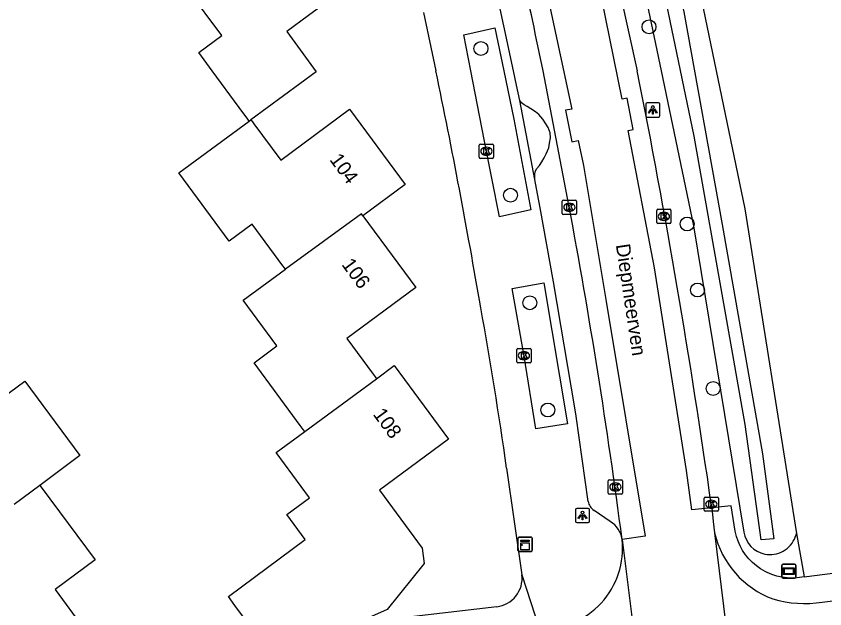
# Model space of a CAD drawing. Extents: x 163427 to 164190, y 380331 to 381641.
# Drawn here: x 163904.6 to 163961.5, y 381212.2 to 381253.8 of the extents above; entities that cross this region are included whole.
import ezdxf

# ---------------------------------------------------------------- set-up
doc = ezdxf.new("R2010")
doc.units = 0
for name, color, linetype in [('IMGEO_Boom', 7, 'Continuous'), ('IMGEO_Erf', 7, 'Continuous'), ('IMGEO_Groenvoorziening', 7, 'Continuous'), ('IMGEO_Kast', 7, 'Continuous'), ('IMGEO_Kolk', 7, 'Continuous'), ('IMGEO_Lichtpunt', 7, 'Continuous'), ('IMGEO_Openbare_ruimte_label', 7, 'Continuous'), ('IMGEO_Pand', 7, 'Continuous'), ('IMGEO_Pand_nummerreeks', 7, 'Continuous'), ('IMGEO_Parkeervlak_open', 7, 'Continuous'), ('IMGEO_Rijbaan_lokaal_gesloten', 7, 'Continuous'), ('IMGEO_Rijbaan_lokaal_open', 7, 'Continuous'), ('IMGEO_Straatnaambord', 7, 'Continuous'), ('IMGEO_Voetpad_open', 7, 'Continuous'), ('IMGEO_Waterloop', 7, 'Continuous')]:
    doc.layers.add(name, color=color, linetype=linetype)

msp = doc.modelspace()

# ---------------------------------------------------------------- linework, layer by layer
at = {"layer": 'IMGEO_Boom'}
for centre in [(163949.16, 381253.1), (163937.333, 381251.576), (163939.411, 381241.248), (163951.839, 381239.226), (163952.575, 381234.582), (163940.773, 381233.686), (163953.673, 381227.649), (163942.035, 381226.141)]:
    msp.add_circle(centre, 0.489, dxfattribs=at)
at = {"layer": 'IMGEO_Erf'}
msp.add_lwpolyline([(163946.949, 381280.126), (163950.911, 381264.377), (163953.894, 381250), (163955.908, 381240.291), (163959.527, 381217.462)], dxfattribs=at)
at = {"layer": 'IMGEO_Groenvoorziening'}
for points in [[(163946.949, 381280.126), (163944.591, 381279.658), (163943.768, 381279.495), (163943.73, 381277.607), (163947.625, 381261.424), (163950.014, 381250), (163952.296, 381239.088), (163955.838, 381217.536)], [(163957.309, 381216.003), (163957.474, 381215.976), (163957.642, 381215.964), (163957.809, 381215.967), (163957.976, 381215.985), (163958.14, 381216.018), (163958.301, 381216.066), (163958.457, 381216.127), (163958.606, 381216.202), (163958.749, 381216.291), (163958.883, 381216.391), (163959.007, 381216.503), (163959.121, 381216.626), (163959.223, 381216.759), (163959.314, 381216.9), (163959.391, 381217.049), (163959.455, 381217.204), (163959.504, 381217.364), (163959.527, 381217.462)], [(163959.527, 381217.462), (163960.076, 381214.403)]]:
    msp.add_lwpolyline(points, dxfattribs=at)
msp.add_arc((163957.687, 381217.838), 1.873, 189.2742, 258.3611, dxfattribs=at)
at = {"layer": 'IMGEO_Kast'}
for p, q in [((163939.939, 381216.261), (163939.939, 381217.102)), ((163939.939, 381217.102), (163939.939, 381216.261)), ((163940.014, 381217.186), (163940.855, 381217.186)), ((163940.855, 381217.186), (163940.014, 381217.186)), ((163940.939, 381217.111), (163940.939, 381216.27)), ((163940.939, 381216.27), (163940.939, 381217.111)), ((163940.864, 381216.186), (163940.023, 381216.186)), ((163940.023, 381216.186), (163940.864, 381216.186))]:
    msp.add_line(p, q, dxfattribs=at)
for points in [[(163940.134, 381216.976), (163940.734, 381216.976), (163940.734, 381216.891), (163940.134, 381216.891), (163940.134, 381216.976)], [(163940.134, 381216.801), (163940.734, 381216.801), (163940.734, 381216.312), (163940.134, 381216.312), (163940.134, 381216.801)]]:
    msp.add_lwpolyline(points, dxfattribs=at)
msp.add_circle((163940.218, 381216.65), 0.0377, dxfattribs=at)
for centre, start, end in [((163940.017, 381217.108), 92.4484, 184.2845), ((163940.017, 381217.108), 92.4484, 184.2845), ((163940.861, 381217.108), 2.4484, 94.2845), ((163940.861, 381217.108), 2.4484, 94.2845), ((163940.017, 381216.264), 182.4484, 274.2845), ((163940.017, 381216.264), 182.4484, 274.2845), ((163940.861, 381216.264), 272.4484, 4.2845), ((163940.861, 381216.264), 272.4484, 4.2845)]:
    msp.add_arc(centre, 0.0779, start, end, dxfattribs=at)
at = {"layer": 'IMGEO_Kolk'}
for p, q in [((163937.217, 381243.917), (163937.217, 381244.769)), ((163937.292, 381244.843), (163938.144, 381244.843)), ((163937.705, 381244.623), (163937.73, 381244.623)), ((163938.218, 381244.769), (163938.218, 381243.917)), ((163938.144, 381243.843), (163937.292, 381243.843)), ((163937.728, 381244.063), (163937.703, 381244.063)), ((163943.132, 381240.9), (163943.984, 381240.9)), ((163943.057, 381239.974), (163943.057, 381240.826)), ((163943.545, 381240.68), (163943.57, 381240.68)), ((163944.058, 381240.826), (163944.058, 381239.974)), ((163943.984, 381239.9), (163943.132, 381239.9)), ((163943.568, 381240.12), (163943.543, 381240.12)), ((163949.705, 381239.334), (163949.705, 381240.186)), ((163949.78, 381240.26), (163950.632, 381240.26)), ((163950.193, 381240.04), (163950.218, 381240.04)), ((163950.706, 381240.186), (163950.706, 381239.334)), ((163950.632, 381239.26), (163949.78, 381239.26)), ((163950.216, 381239.48), (163950.191, 381239.48)), ((163939.858, 381229.537), (163939.858, 381230.389)), ((163939.933, 381230.463), (163940.785, 381230.463)), ((163940.346, 381230.243), (163940.371, 381230.243)), ((163940.859, 381230.389), (163940.859, 381229.537)), ((163940.369, 381229.683), (163940.344, 381229.683)), ((163940.785, 381229.463), (163939.933, 381229.463)), ((163946.295, 381220.298), (163946.295, 381221.15)), ((163946.37, 381221.224), (163947.222, 381221.224)), ((163946.783, 381221.004), (163946.808, 381221.004)), ((163947.296, 381221.15), (163947.296, 381220.298)), ((163946.806, 381220.444), (163946.781, 381220.444)), ((163947.222, 381220.224), (163946.37, 381220.224)), ((163953.044, 381219.087), (163953.044, 381219.939)), ((163953.119, 381220.013), (163953.971, 381220.013)), ((163954.045, 381219.939), (163954.045, 381219.087)), ((163953.532, 381219.793), (163953.557, 381219.793)), ((163953.971, 381219.013), (163953.119, 381219.013)), ((163953.555, 381219.233), (163953.53, 381219.233))]:
    msp.add_line(p, q, dxfattribs=at)
for points in [[(163937.217, 381243.917), (163937.217, 381244.769)], [(163937.292, 381244.843), (163938.144, 381244.843)], [(163937.538, 381244.543), (163937.661, 381244.543), (163937.661, 381244.392), (163937.791, 381244.543), (163937.955, 381244.543), (163937.809, 381244.392), (163937.962, 381244.143), (163937.81, 381244.143), (163937.725, 381244.307), (163937.661, 381244.24), (163937.661, 381244.143), (163937.538, 381244.143), (163937.538, 381244.543)], [(163938.218, 381244.769), (163938.218, 381243.917)], [(163938.144, 381243.843), (163937.292, 381243.843)], [(163943.132, 381240.9), (163943.984, 381240.9)], [(163943.057, 381239.974), (163943.057, 381240.826)], [(163943.378, 381240.6), (163943.501, 381240.6), (163943.501, 381240.449), (163943.631, 381240.6), (163943.795, 381240.6), (163943.649, 381240.449), (163943.802, 381240.2), (163943.65, 381240.2), (163943.565, 381240.364), (163943.501, 381240.297), (163943.501, 381240.2), (163943.378, 381240.2), (163943.378, 381240.6)], [(163944.058, 381240.826), (163944.058, 381239.974)], [(163943.984, 381239.9), (163943.132, 381239.9)], [(163949.705, 381239.334), (163949.705, 381240.186)], [(163949.78, 381240.26), (163950.632, 381240.26)], [(163950.026, 381239.96), (163950.149, 381239.96), (163950.149, 381239.809), (163950.279, 381239.96), (163950.443, 381239.96), (163950.297, 381239.809), (163950.45, 381239.56), (163950.298, 381239.56), (163950.213, 381239.724), (163950.149, 381239.657), (163950.149, 381239.56), (163950.026, 381239.56), (163950.026, 381239.96)], [(163950.706, 381240.186), (163950.706, 381239.334)], [(163950.632, 381239.26), (163949.78, 381239.26)], [(163939.858, 381229.537), (163939.858, 381230.389)], [(163939.933, 381230.463), (163940.785, 381230.463)], [(163940.179, 381230.163), (163940.302, 381230.163), (163940.302, 381230.012), (163940.432, 381230.163), (163940.596, 381230.163), (163940.45, 381230.012), (163940.603, 381229.763), (163940.451, 381229.763), (163940.366, 381229.927), (163940.302, 381229.86), (163940.302, 381229.763), (163940.179, 381229.763), (163940.179, 381230.163)], [(163940.859, 381230.389), (163940.859, 381229.537)], [(163940.785, 381229.463), (163939.933, 381229.463)], [(163946.295, 381220.298), (163946.295, 381221.15)], [(163946.37, 381221.224), (163947.222, 381221.224)], [(163947.296, 381221.15), (163947.296, 381220.298)], [(163946.616, 381220.924), (163946.739, 381220.924), (163946.739, 381220.773), (163946.869, 381220.924), (163947.033, 381220.924), (163946.887, 381220.773), (163947.04, 381220.524), (163946.888, 381220.524), (163946.803, 381220.688), (163946.739, 381220.621), (163946.739, 381220.524), (163946.616, 381220.524), (163946.616, 381220.924)], [(163947.222, 381220.224), (163946.37, 381220.224)], [(163953.044, 381219.087), (163953.044, 381219.939)], [(163953.119, 381220.013), (163953.971, 381220.013)], [(163954.045, 381219.939), (163954.045, 381219.087)], [(163953.365, 381219.713), (163953.488, 381219.713), (163953.488, 381219.562), (163953.618, 381219.713), (163953.782, 381219.713), (163953.636, 381219.562), (163953.789, 381219.313), (163953.637, 381219.313), (163953.552, 381219.477), (163953.488, 381219.41), (163953.488, 381219.313), (163953.365, 381219.313), (163953.365, 381219.713)], [(163953.971, 381219.013), (163953.119, 381219.013)]]:
    msp.add_lwpolyline(points, dxfattribs=at)
for centre, start, end in [((163937.294, 381244.767), 91.552, 178.448), ((163937.294, 381244.767), 91.552, 178.448), ((163938.142, 381244.767), 1.552, 88.448), ((163938.142, 381244.767), 1.552, 88.448), ((163937.294, 381243.919), 181.552, 268.448), ((163937.294, 381243.919), 181.552, 268.448), ((163938.142, 381243.919), 271.552, 358.448), ((163938.142, 381243.919), 271.552, 358.448), ((163943.134, 381240.824), 91.552, 178.448), ((163943.134, 381240.824), 91.552, 178.448), ((163943.982, 381240.824), 1.552, 88.448), ((163943.982, 381240.824), 1.552, 88.448), ((163943.134, 381239.976), 181.552, 268.448), ((163943.134, 381239.976), 181.552, 268.448), ((163943.982, 381239.976), 271.552, 358.448), ((163943.982, 381239.976), 271.552, 358.448), ((163949.782, 381240.184), 91.552, 178.448), ((163949.782, 381240.184), 91.552, 178.448), ((163950.63, 381240.184), 1.552, 88.448), ((163950.63, 381240.184), 1.552, 88.448), ((163949.782, 381239.336), 181.552, 268.448), ((163949.782, 381239.336), 181.552, 268.448), ((163950.63, 381239.336), 271.552, 358.448), ((163950.63, 381239.336), 271.552, 358.448), ((163939.935, 381230.387), 91.552, 178.448), ((163939.935, 381230.387), 91.552, 178.448), ((163940.783, 381230.387), 1.552, 88.448), ((163940.783, 381230.387), 1.552, 88.448), ((163939.935, 381229.539), 181.552, 268.448), ((163939.935, 381229.539), 181.552, 268.448), ((163940.783, 381229.539), 271.552, 358.448), ((163940.783, 381229.539), 271.552, 358.448), ((163946.372, 381221.148), 91.552, 178.448), ((163946.372, 381221.148), 91.552, 178.448), ((163947.22, 381221.148), 1.552, 88.448), ((163947.22, 381221.148), 1.552, 88.448), ((163946.372, 381220.3), 181.552, 268.448), ((163946.372, 381220.3), 181.552, 268.448), ((163947.22, 381220.3), 271.552, 358.448), ((163947.22, 381220.3), 271.552, 358.448), ((163953.121, 381219.937), 91.552, 178.448), ((163953.121, 381219.937), 91.552, 178.448), ((163953.969, 381219.937), 1.552, 88.448), ((163953.969, 381219.937), 1.552, 88.448), ((163953.121, 381219.089), 181.552, 268.448), ((163953.121, 381219.089), 181.552, 268.448), ((163953.969, 381219.089), 271.552, 358.448), ((163953.969, 381219.089), 271.552, 358.448)]:
    msp.add_arc(centre, 0.0765, start, end, dxfattribs=at)
for centre, major_axis, ratio, start_param, end_param in [((163937.704, 381244.343), (-0.387, 0.002), 0.722429, 4.712389, 7.853982), ((163937.729, 381244.343), (-0.39, 0.002), 0.717154, 1.570796, 4.712389), ((163943.544, 381240.4), (-0.387, 0.002), 0.722429, 4.712389, 7.853982), ((163943.569, 381240.4), (-0.39, 0.002), 0.717154, 1.570796, 4.712389), ((163950.192, 381239.76), (-0.387, 0.002), 0.722429, 4.712389, 7.853982), ((163950.217, 381239.76), (-0.39, 0.002), 0.717154, 1.570796, 4.712389), ((163940.345, 381229.963), (-0.387, 0.002), 0.722429, 4.712389, 7.853982), ((163940.37, 381229.963), (-0.39, 0.002), 0.717154, 1.570796, 4.712389), ((163946.782, 381220.724), (-0.387, 0.002), 0.722429, 4.712389, 7.853982), ((163946.807, 381220.724), (-0.39, 0.002), 0.717154, 1.570796, 4.712389), ((163953.531, 381219.513), (-0.387, 0.002), 0.722429, 4.712389, 7.853982), ((163953.556, 381219.513), (-0.39, 0.002), 0.717154, 1.570796, 4.712389)]:
    msp.add_ellipse(centre, major_axis=major_axis, ratio=ratio, start_param=start_param, end_param=end_param, dxfattribs=at)
at = {"layer": 'IMGEO_Lichtpunt'}
for p, q in [((163949.828, 381247.749), (163949.02, 381247.749)), ((163949.828, 381247.749), (163949.02, 381247.749)), ((163948.926, 381247.654), (163948.926, 381246.847)), ((163948.926, 381247.654), (163948.926, 381246.847)), ((163949.922, 381246.847), (163949.922, 381247.654)), ((163949.922, 381246.847), (163949.922, 381247.654)), ((163949.02, 381246.753), (163949.828, 381246.753)), ((163949.02, 381246.753), (163949.828, 381246.753)), ((163943.978, 381219.119), (163943.978, 381218.312)), ((163943.978, 381219.119), (163943.978, 381218.312)), ((163944.88, 381219.214), (163944.072, 381219.214)), ((163944.88, 381219.214), (163944.072, 381219.214)), ((163944.974, 381218.312), (163944.974, 381219.119)), ((163944.974, 381218.312), (163944.974, 381219.119)), ((163944.072, 381218.218), (163944.88, 381218.218)), ((163944.072, 381218.218), (163944.88, 381218.218))]:
    msp.add_line(p, q, dxfattribs=at)
for points in [[(163949.3, 381247.318), (163949.339, 381247.29), (163949.151, 381247.028), (163949.113, 381247.055), (163949.3, 381247.318)], [(163949.402, 381247.27), (163949.449, 381247.27), (163949.449, 381246.948), (163949.402, 381246.948), (163949.402, 381247.27)], [(163949.512, 381247.29), (163949.55, 381247.317), (163949.737, 381247.055), (163949.698, 381247.027), (163949.512, 381247.29)], [(163944.352, 381218.783), (163944.391, 381218.755), (163944.203, 381218.493), (163944.165, 381218.52), (163944.352, 381218.783)], [(163944.454, 381218.735), (163944.501, 381218.735), (163944.501, 381218.413), (163944.454, 381218.413), (163944.454, 381218.735)], [(163944.564, 381218.755), (163944.602, 381218.782), (163944.789, 381218.52), (163944.75, 381218.492), (163944.564, 381218.755)]]:
    msp.add_lwpolyline(points, dxfattribs=at)
for centre in [(163949.425, 381247.452), (163944.477, 381218.917)]:
    msp.add_circle(centre, 0.0994, dxfattribs=at)
for centre, start, end in [((163949.02, 381247.654), 90, 180), ((163949.02, 381247.654), 90, 180), ((163949.828, 381247.654), 0, 90), ((163949.828, 381247.654), 0, 90), ((163949.02, 381246.847), 180, 270), ((163949.02, 381246.847), 180, 270), ((163949.828, 381246.847), 270, 0), ((163949.828, 381246.847), 270, 360), ((163944.072, 381219.119), 90, 180), ((163944.072, 381219.119), 90, 180), ((163944.88, 381219.119), 0, 90), ((163944.88, 381219.119), 0, 90), ((163944.072, 381218.312), 180, 270), ((163944.072, 381218.312), 180, 270), ((163944.88, 381218.312), 270, 0), ((163944.88, 381218.312), 270, 360)]:
    msp.add_arc(centre, 0.0946, start, end, dxfattribs=at)
at = {"layer": 'IMGEO_Pand'}
for points in [[(163923.541, 381260.701), (163925.042, 381261.788), (163928.858, 381256.586), (163925.203, 381253.905), (163923.664, 381252.776), (163925.746, 381249.938), (163921.142, 381246.559)], [(163921.018, 381246.468), (163920.924, 381246.596), (163920.319, 381247.421), (163918.427, 381250), (163917.477, 381251.296), (163919.089, 381252.478), (163916.694, 381255.744)], [(163921.142, 381246.559), (163921.255, 381246.406), (163921.349, 381246.279), (163923.241, 381243.723), (163928.087, 381247.31), (163932.004, 381242.003), (163929.027, 381239.809)], [(163921.018, 381246.468), (163921.142, 381246.559)], [(163923.577, 381236.038), (163923.501, 381236.141), (163923.394, 381236.286), (163921.229, 381239.216), (163919.623, 381238.029), (163916.069, 381242.837), (163921.018, 381246.468)], [(163929.027, 381239.809), (163928.932, 381239.938), (163923.577, 381236.038)], [(163929.027, 381239.809), (163932.757, 381234.753), (163927.885, 381231.164), (163929.745, 381228.65), (163929.881, 381228.466), (163929.973, 381228.341)], [(163924.929, 381224.636), (163924.829, 381224.772), (163924.62, 381225.054), (163921.364, 381229.46), (163922.97, 381230.647), (163920.592, 381233.864), (163923.577, 381236.038)], [(163929.973, 381228.341), (163931.237, 381229.27), (163935.058, 381224.076), (163930.198, 381220.5), (163933.192, 381216.427), (163933.327, 381215.334), (163930.724, 381212.101), (163925.359, 381209.706), (163922.998, 381208.373), (163920.026, 381212.394), (163919.557, 381213.029), (163924.967, 381217.028), (163923.674, 381218.778), (163925.279, 381219.965), (163922.918, 381223.159), (163924.929, 381224.636)], [(163900.412, 381228.801), (163902.419, 381226.093), (163905.23, 381228.176), (163909.118, 381222.931), (163906.302, 381220.836)], [(163924.929, 381224.636), (163929.973, 381228.341)], [(163906.302, 381220.836), (163904.482, 381219.482)], [(163906.302, 381220.836), (163906.393, 381220.713), (163910.185, 381215.595), (163907.365, 381213.506), (163909.376, 381210.792)]]:
    msp.add_lwpolyline(points, dxfattribs=at)
at = {"layer": 'IMGEO_Parkeervlak_open'}
msp.add_lwpolyline([(163941.127, 381242.354), (163941.114, 381242.759), (163941.176, 381242.958), (163941.275, 381243.128), (163941.449, 381243.349), (163941.628, 381243.606), (163941.79, 381243.879), (163941.918, 381244.152), (163942.101, 381244.584), (163942.162, 381244.903), (163942.224, 381245.288), (163942.215, 381245.638), (163942.058, 381246.015), (163941.891, 381246.283), (163941.684, 381246.607), (163941.4, 381246.924), (163941.171, 381247.114), (163940.853, 381247.321), (163940.597, 381247.483), (163940.368, 381247.607), (163940.194, 381247.75), (163940.062, 381247.913)], dxfattribs=at)
at = {"layer": 'IMGEO_Rijbaan_lokaal_gesloten'}
for points in [[(163912.249, 381359.295), (163913.697, 381359.629), (163921.907, 381330.645), (163925.185, 381318.778), (163924.817, 381318.679), (163925.405, 381316.489), (163925.802, 381316.596), (163930.68, 381299.334), (163933.228, 381290.176), (163942.098, 381254.961), (163943.722, 381247.313), (163943.287, 381247.227), (163943.726, 381245.01), (163944.183, 381245.1), (163944.552, 381243.335), (163946.144, 381233.78), (163948.882, 381217.269), (163947.265, 381217.038)], [(163953.57, 381219.255), (163952.161, 381219.119), (163951.806, 381221.884), (163949.541, 381236.14), (163947.702, 381245.797), (163948.052, 381245.866), (163947.613, 381248.083), (163947.279, 381248.017), (163944.361, 381262.334), (163940.492, 381277.062), (163941.823, 381277.416)], [(163941.823, 381277.416), (163942.486, 381274.934), (163944.765, 381266.145), (163948.335, 381250)], [(163943.519, 381240.555), (163941.708, 381250)], [(163953.54, 381219.513), (163953.57, 381219.255)], [(163953.57, 381219.255), (163953.683, 381218.285), (163953.779, 381217.501)], [(163947.265, 381217.038), (163949.305, 381200.709)], [(163953.779, 381217.501), (163955.843, 381200.674)]]:
    msp.add_lwpolyline(points, dxfattribs=at)
for centre, radius, start, end in [((163522.519, 381163.934), 427.933, 11.60247, 13.52023), ((163385.867, 381138.283), 573.456, 8.143357, 11.233859), ((163518.613, 381160.815), 432.324, 7.47236, 10.62875)]:
    msp.add_arc(centre, radius, start, end, dxfattribs=at)
at = {"layer": 'IMGEO_Rijbaan_lokaal_open'}
msp.add_lwpolyline([(163961.351, 381212.629), (163974.075, 381214.227)], dxfattribs=at)
for centre, radius, start, end in [((163941.609, 381216.413), 5.691, 268.4338, 6.3074), ((163960.137, 381218.969), 6.525, 193.0053, 249.7663), ((163960.095, 381220.375), 7.848, 253.604, 279.2084)]:
    msp.add_arc(centre, radius, start, end, dxfattribs=at)
at = {"layer": 'IMGEO_Straatnaambord'}
for p, q in [((163958.596, 381215.297), (163959.386, 381215.297)), ((163959.386, 381215.297), (163958.596, 381215.297)), ((163958.496, 381214.397), (163958.496, 381215.197)), ((163958.496, 381215.197), (163958.496, 381214.397)), ((163959.486, 381215.197), (163959.486, 381214.397)), ((163959.486, 381214.397), (163959.486, 381215.197)), ((163959.386, 381214.297), (163958.596, 381214.297)), ((163958.596, 381214.297), (163959.386, 381214.297))]:
    msp.add_line(p, q, dxfattribs=at)
for points in [[(163958.597, 381215.029), (163959.385, 381215.029), (163959.385, 381214.565), (163958.597, 381214.565), (163958.597, 381215.029)], [(163958.662, 381214.964), (163958.662, 381214.63), (163959.32, 381214.63), (163959.32, 381214.964), (163958.662, 381214.964)]]:
    msp.add_lwpolyline(points, dxfattribs=at)
for centre, start, end in [((163958.596, 381215.197), 90, 180), ((163958.596, 381215.197), 90, 180), ((163959.386, 381215.197), 0, 90), ((163959.386, 381215.197), 360, 90), ((163958.596, 381214.397), 180, 270), ((163958.596, 381214.397), 180, 270), ((163959.386, 381214.397), 270, 0), ((163959.386, 381214.397), 270, 0)]:
    msp.add_arc(centre, 0.1, start, end, dxfattribs=at)
at = {"layer": 'IMGEO_Voetpad_open'}
for points in [[(163940.062, 381247.913), (163939.835, 381248.988), (163939.627, 381250), (163938.955, 381253.175), (163937.51, 381259.832), (163936.359, 381264.784), (163935.892, 381266.688), (163934.592, 381271.826), (163933.019, 381277.636), (163931.635, 381282.748)], [(163933.3, 381254.106), (163934.167, 381250)], [(163938.305, 381253.03), (163938.938, 381250), (163939.646, 381246.606), (163940.84, 381240.228), (163938.639, 381239.731), (163937.567, 381245.174), (163936.622, 381250), (163936.125, 381252.542), (163938.305, 381253.03)], [(163941.127, 381242.354), (163940.062, 381247.913)], [(163944.882, 381219.713), (163944.027, 381225.716), (163943.966, 381226.145), (163942.427, 381235.164), (163941.491, 381240.359), (163941.313, 381241.342), (163941.127, 381242.354)], [(163941.75, 381235.096), (163943.423, 381225.172), (163941.191, 381224.82), (163940.366, 381229.927), (163939.539, 381234.696), (163941.75, 381235.096)], [(163939.142, 381222.056), (163940.216, 381214.537)], [(163960.076, 381214.403), (163959.414, 381214.318), (163959.234, 381214.313), (163958.87, 381214.328), (163958.508, 381214.376), (163958.152, 381214.455), (163957.805, 381214.566), (163957.469, 381214.708), (163957.324, 381214.781), (163957.01, 381214.964), (163956.713, 381215.175), (163956.436, 381215.411), (163956.182, 381215.672), (163955.952, 381215.954), (163955.748, 381216.255), (163955.571, 381216.574), (163955.424, 381216.907), (163955.308, 381217.251), (163955.222, 381217.605), (163954.949, 381219.4), (163953.57, 381219.255)], [(163946.432, 381218.288), (163945.289, 381219.077)], [(163960.076, 381214.403), (163973.754, 381216.166)], [(163940.216, 381214.537), (163941.453, 381210.724)], [(163938.44, 381212.302), (163932.204, 381211.561)]]:
    msp.add_lwpolyline(points, dxfattribs=at)
for centre, radius, start, end in [((163443.56, 381148.488), 500.999, 9.7504, 11.6902), ((163632.552, 381178.37), 309.687, 8.10941, 10.22327), ((163945.839, 381219.877), 0.971, 189.7285, 235.5049), ((163945.561, 381216.805), 1.72, 7.7876, 59.5713), ((163938.218, 381214.302), 2.012, 276.3433, 6.7132)]:
    msp.add_arc(centre, radius, start, end, dxfattribs=at)
at = {"layer": 'IMGEO_Waterloop'}
msp.add_lwpolyline([(163945.788, 381278.484), (163951.599, 381254.151), (163954.309, 381239.202), (163957.143, 381223.063), (163957.944, 381217.087), (163957.04, 381216.995), (163955.931, 381225.126), (163954.566, 381232.837), (163952.348, 381245.404), (163949.802, 381257.601), (163947.42, 381267.868), (163944.766, 381278.235), (163945.788, 381278.484)], dxfattribs=at)

# ---------------------------------------------------------------- texts
at = {"layer": 'IMGEO_Openbare_ruimte_label'}
msp.add_text('Diepmeerven', height=1, rotation=278.4543, dxfattribs=at).set_placement((163946.822, 381237.761))
at = {"layer": 'IMGEO_Pand_nummerreeks'}
for s, rotation, p in [('104', 306.4284, (163926.642, 381243.744)), ('106', 306.417, (163927.488, 381236.369)), ('108', 306.3425, (163929.697, 381225.828))]:
    msp.add_text(s, height=1, rotation=rotation, dxfattribs=at).set_placement(p)

doc.saveas('drawing.dxf')
